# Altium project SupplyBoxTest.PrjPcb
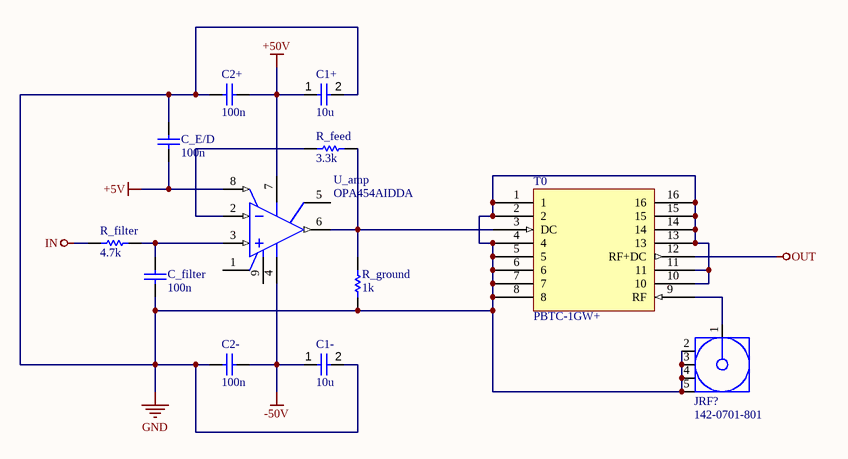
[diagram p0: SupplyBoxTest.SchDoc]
1 sheet, 12 parts. Net scope: global (net labels, ports and power ports of the same name join across sheets).
Board file: SupplyBoxTest.PcbDoc

## Sheet SupplyBoxTest.SchDoc
size A; SheetNumber: 1; SheetTotal: 1

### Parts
C1+  10u  [PCBComponent_1]
C1-  10u  [PCBComponent_1]
C2+  100n  [CAPC2013X135X45ML10T25]
C2-  100n  [CAPC2013X135X45ML10T25]
C_E/D  100n  [CAPC2013X135X45ML10T25]
C_filter  100n  [CAPC2013X145X48NL20T23]
JRF?  142-0701-801  [CINC-142-0701-801_V]
R_feed  3.3k  [RESC2013X60X35ML10T20]
R_filter  4.7k  [RESC2013X60X35NL10T20]
R_ground  1k  [RESC2013X60X35ML10T20]
T0  PBTC-1GW+  [PBTC-1GW+]
U_amp  OPA454AIDDA  [DDA0008C_L]

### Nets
+5V: C_E/D.2 U_amp.8(E/D)
+50V: C1+.1 C2+.2 U_amp.7(V+)
-50V: C1-.1 C2-.2 U_amp.4(V-)
GND: C1+.2 C1-.2 C2+.1 C2-.1 C_E/D.1 C_filter.1 JRF?.2 JRF?.3 JRF?.4 JRF?.5 R_ground.1 T0.1 T0.2 T0.4 T0.5 T0.6 T0.7 T0.8 T0.10 T0.11 T0.13 T0.14 T0.15 T0.16
IN: R_filter.1
OUT: T0.12(RF+DC)
NetC_filter_2: C_filter.2 R_filter.2 U_amp.3(IN+)
NetJRF?_1: JRF?.1 T0.9(RF)
NetR_feed_1: R_feed.1 U_amp.2(IN-)
NetR_feed_2: R_feed.2 R_ground.2 T0.3(DC) U_amp.6(OUT)

Not connected (* = marked no-connect by the designer): U_amp 1(E/D_COM) 5(STATUS_FLAG) 9(EP)

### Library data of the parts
C1+ C1- = CMP-001-00083-1: Aluminum Electrolytic Capacitor, Polarized, Aluminum (solid Polymer), 50V, 20% +Tol, 20% -Tol, 10uF, Surface Mount, 2121
C2+ C2- C_E/D = CMP-2100-03644-1: Chip Capacitor, 0.1 uF, +/- 10%, 50 V, -55 to 125 degC, 0805 (2012 Metric), RoHS, Tape and Reel; Manufacturer: Murata; Voltage: 50V; Capacitance: 100nF; Insulation Resistance: 10GR; Dielectric Material: Ceramic; Dielectric: X7R
C_filter = CMP-2007-03167-1: Manufacturer: Vitramon; Part Number: VJ0805Y104KNAAT
JRF? = CMP-2000-05490-1: SMA End Launch Jack Receptacle, 50 Ohm, 0 to 18 GHz, -65 to 165 degC, 5-Pin SMD, RoHS, Bulk; Manufacturer: EmersonConnectivitySolutions; Connector Type: JackPCB; Gender: Jack(Female); Impedance: 50Ohms; Brand: Johnson/EmersonConnectivitySolutions; Body Material: Brass; Body Style: Straight; Maximum Frequency: 18GHz
R_feed = CMP-1013-00567-2: Chip Resistor, 3.3 KOhm, +/- 1%, 0.125 W, -55 to 155 degC, 0805 (2012 Metric), RoHS, Tape and Reel; Manufacturer: Yageo; Voltage Rating: 150V; Max Power Dissipation: 125mW; Temperature Coefficient: 100ppm/degreesC
R_filter = CMP-1659-00011-4: Chip Resistor, 47 KOhm, +/- 1%, 0.125 W, -55 to 155 degC, 0805 (2012 Metric), RoHS, Tape and Reel; Manufacturer: Yageo; Voltage Rating: 150 V
R_ground = CMP-2100-03671-1: Chip Resistor, 1 KOhm, +/- 1%, 125 mW, -55 to 155 degC, 0805 (2012 Metric), RoHS, Tape and Reel; Manufacturer: Yageo; Temperature Coefficient: 100ppm/degreesC; Voltage Rating (DC): 150V; Max Power Dissipation: 125mW; Resistance: 1KOhm
T0 = CMP-00025-00003-1: Monitor TEE DC Block, 0.1MHz Min, 1000MHz Max, 1dB Insertion Loss-Max
U_amp = CMP-0017-00714-2: High Voltage (100V), High-Current (50mA) Operational Amplifier, G=1 Stable, 10 to 100 V, -55 to 125 degC, 8-pin SOP (DDA8), Green (RoHS & no Sb/Br); Manufacturer: Texas Instruments; Number of Channels: 1; CMRR(Min)(dB): 100; Rating: Catalog; Total Supply Voltage(Min)(+5V is 5, +/-5V is 10): 10; Offset Drift(Typ)(uV/C): 1.6; Vn at 1kHz(Typ)(nV/rtHz): 47; Slew Rate(Typ)(V/us): 13; Sub Family: General Purpose Amplifier, High Output Current Amplifier (>=50mA), High Supply Voltage Amplifier (>=30V), Precision Amplifier; Iq per channel(Max)(mA): 4; GBW(Typ)(MHz): 2.5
